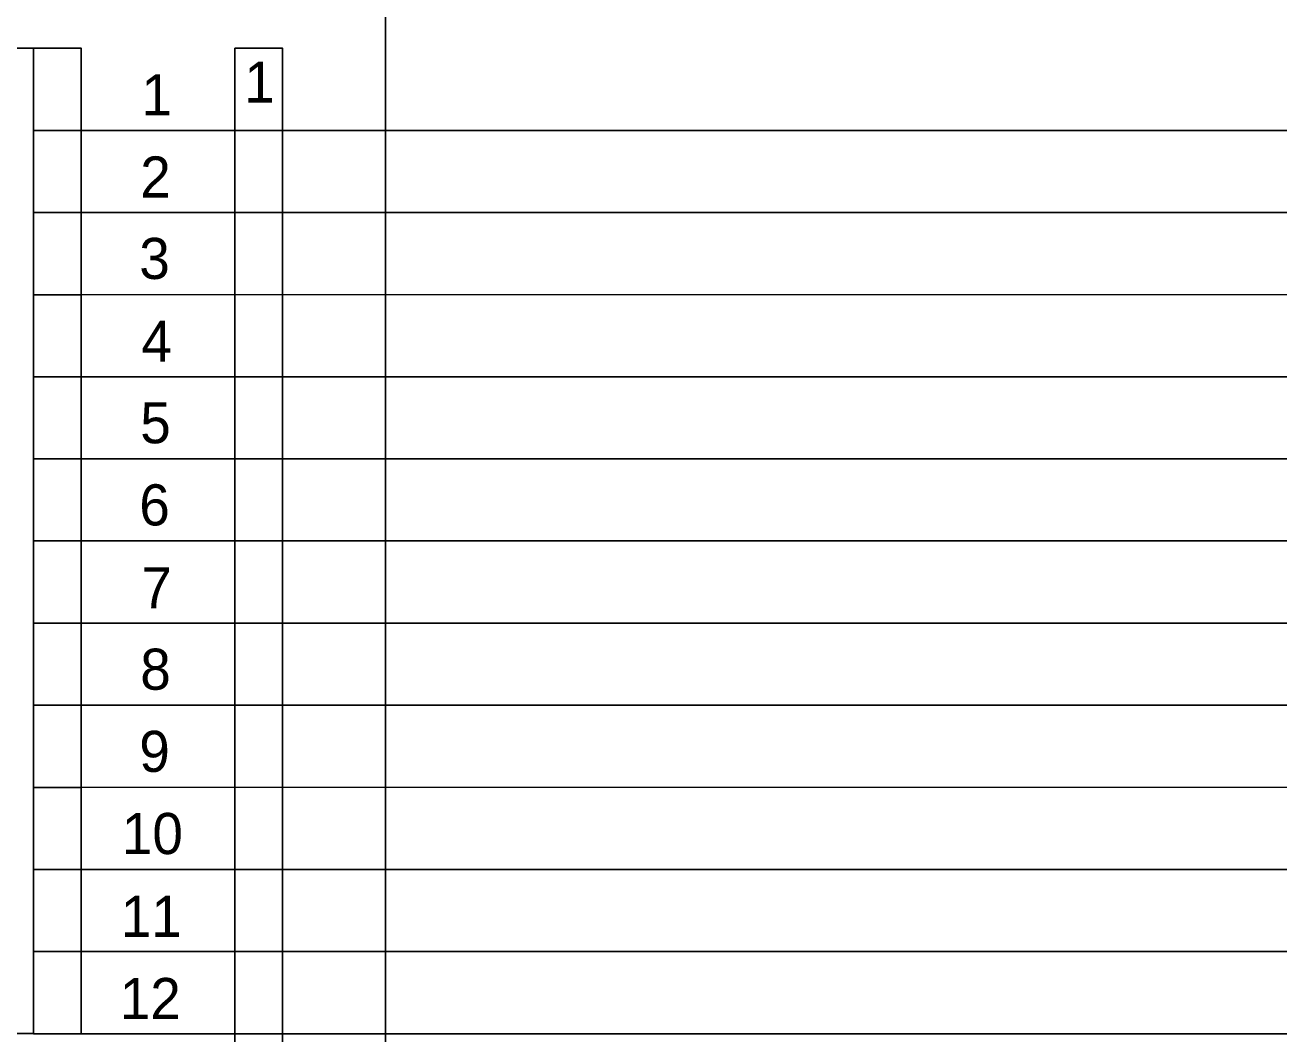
# Model space of a CAD drawing. Extents: x 1901 to 2519, y -3585 to -3154.
# Drawn here: x 2113 to 2166.7, y -3245.2 to -3202 of the extents above; entities that cross this region are included whole.
import ezdxf

# ---------------------------------------------------------------- set-up
doc = ezdxf.new("R2010")
doc.units = 0
doc.layers.add('rozvláknění', color=7, linetype='Continuous')

msp = doc.modelspace()

# ---------------------------------------------------------------- linework, layer by layer
at = {"layer": 'rozvláknění'}
for p, q in [((2115.435, -3206.527), (2247.063, -3206.526)), ((2115.435, -3210.045), (2247.063, -3210.044)), ((2115.435, -3213.563), (2247.063, -3213.562)), ((2115.435, -3217.081), (2247.063, -3217.08)), ((2115.435, -3220.599), (2247.063, -3220.598)), ((2115.435, -3224.117), (2247.063, -3224.117)), ((2115.435, -3227.636), (2247.063, -3227.635)), ((2115.435, -3231.154), (2247.063, -3231.153)), ((2115.435, -3234.672), (2247.063, -3234.671)), ((2115.435, -3238.19), (2247.063, -3238.189)), ((2115.435, -3241.708), (2247.063, -3241.708)), ((2115.435, -3245.227), (2247.063, -3245.226))]:
    msp.add_line(p, q, dxfattribs=at)
for points in [[(2094.462, -3178.545), (2128.46, -3178.544), (2128.46, -3571.465), (2094.462, -3571.465)], [(2110.606, -3203.008), (2113.393, -3203.008), (2113.393, -3245.223), (2110.606, -3245.223)], [(2113.393, -3203.008), (2115.435, -3203.008), (2115.435, -3206.527), (2113.393, -3206.527)], [(2113.393, -3203.008), (2115.435, -3203.008), (2115.435, -3206.527), (2113.393, -3206.527)], [(2124.059, -3287.481), (2122.017, -3287.481), (2122.017, -3203.008), (2124.059, -3203.008)], [(2124.059, -3245.227), (2122.017, -3245.227), (2122.017, -3203.008), (2124.059, -3203.008)], [(2113.393, -3206.527), (2115.435, -3206.527), (2115.435, -3210.045), (2113.393, -3210.045)], [(2113.393, -3206.527), (2115.435, -3206.527), (2115.435, -3210.045), (2113.393, -3210.045)], [(2113.393, -3210.045), (2115.435, -3210.045), (2115.435, -3213.563), (2113.393, -3213.563)], [(2113.393, -3210.045), (2115.435, -3210.045), (2115.435, -3213.563), (2113.393, -3213.563)], [(2113.393, -3213.563), (2115.435, -3213.563), (2115.435, -3217.081), (2113.393, -3217.081)], [(2113.393, -3213.563), (2115.435, -3213.563), (2115.435, -3217.081), (2113.393, -3217.081)], [(2113.393, -3217.081), (2115.435, -3217.081), (2115.435, -3220.599), (2113.393, -3220.599)], [(2113.393, -3217.081), (2115.435, -3217.081), (2115.435, -3220.599), (2113.393, -3220.599)], [(2113.393, -3220.599), (2115.435, -3220.599), (2115.435, -3224.117), (2113.393, -3224.117)], [(2113.393, -3220.599), (2115.435, -3220.599), (2115.435, -3224.117), (2113.393, -3224.117)], [(2113.393, -3224.117), (2115.435, -3224.117), (2115.435, -3227.636), (2113.393, -3227.636)], [(2113.393, -3224.117), (2115.435, -3224.117), (2115.435, -3227.636), (2113.393, -3227.636)], [(2113.393, -3227.636), (2115.435, -3227.636), (2115.435, -3231.154), (2113.393, -3231.154)], [(2113.393, -3227.636), (2115.435, -3227.636), (2115.435, -3231.154), (2113.393, -3231.154)], [(2113.393, -3231.154), (2115.435, -3231.154), (2115.435, -3234.672), (2113.393, -3234.672)], [(2113.393, -3231.154), (2115.435, -3231.154), (2115.435, -3234.672), (2113.393, -3234.672)], [(2113.393, -3234.672), (2115.435, -3234.672), (2115.435, -3238.19), (2113.393, -3238.19)], [(2113.393, -3234.672), (2115.435, -3234.672), (2115.435, -3238.19), (2113.393, -3238.19)], [(2113.393, -3238.19), (2115.435, -3238.19), (2115.435, -3241.708), (2113.393, -3241.708)], [(2113.393, -3238.19), (2115.435, -3238.19), (2115.435, -3241.708), (2113.393, -3241.708)], [(2113.393, -3241.708), (2115.435, -3241.708), (2115.435, -3245.227), (2113.393, -3245.227)], [(2113.393, -3241.708), (2115.435, -3241.708), (2115.435, -3245.227), (2113.393, -3245.227)]]:
    msp.add_lwpolyline(points, close=True, dxfattribs=at)
for points in [[(2113.393, -3206.527), (2115.435, -3206.527), (2115.435, -3203.008), (2113.393, -3203.008), (2113.393, -3206.527)], [(2113.393, -3206.527), (2115.435, -3206.527), (2115.435, -3203.008), (2113.393, -3203.008), (2113.393, -3206.527)], [(2113.393, -3206.527), (2115.435, -3206.527), (2115.435, -3203.008), (2113.393, -3203.008), (2113.393, -3206.527)], [(2113.393, -3206.527), (2115.435, -3206.527), (2115.435, -3203.008), (2113.393, -3203.008), (2113.393, -3206.527)], [(2113.393, -3206.527), (2115.435, -3206.527), (2115.435, -3203.008), (2113.393, -3203.008), (2113.393, -3206.527)], [(2113.393, -3206.527), (2115.435, -3206.527), (2115.435, -3203.008), (2113.393, -3203.008), (2113.393, -3206.527)], [(2113.393, -3206.527), (2115.435, -3206.527), (2115.435, -3203.008), (2113.393, -3203.008), (2113.393, -3206.527)], [(2113.393, -3206.527), (2115.435, -3206.527), (2115.435, -3203.008), (2113.393, -3203.008), (2113.393, -3206.527)], [(2113.393, -3206.527), (2115.435, -3206.527), (2115.435, -3203.008), (2113.393, -3203.008), (2113.393, -3206.527)], [(2113.393, -3206.527), (2115.435, -3206.527), (2115.435, -3203.008), (2113.393, -3203.008), (2113.393, -3206.527)], [(2124.059, -3203.008), (2122.017, -3203.008), (2122.017, -3245.227), (2124.059, -3245.227), (2124.059, -3203.008)], [(2124.059, -3203.008), (2122.017, -3203.008), (2122.017, -3245.227), (2124.059, -3245.227), (2124.059, -3203.008)], [(2124.059, -3203.008), (2122.017, -3203.008), (2122.017, -3245.227), (2124.059, -3245.227), (2124.059, -3203.008)], [(2124.059, -3203.008), (2122.017, -3203.008), (2122.017, -3245.227), (2124.059, -3245.227), (2124.059, -3203.008)], [(2124.059, -3203.008), (2122.017, -3203.008), (2122.017, -3245.227), (2124.059, -3245.227), (2124.059, -3203.008)], [(2124.059, -3203.008), (2122.017, -3203.008), (2122.017, -3245.227), (2124.059, -3245.227), (2124.059, -3203.008)], [(2113.393, -3210.045), (2115.435, -3210.045), (2115.435, -3206.527), (2113.393, -3206.527), (2113.393, -3210.045)], [(2113.393, -3210.045), (2115.435, -3210.045), (2115.435, -3206.527), (2113.393, -3206.527), (2113.393, -3210.045)], [(2113.393, -3210.045), (2115.435, -3210.045), (2115.435, -3206.527), (2113.393, -3206.527), (2113.393, -3210.045)], [(2113.393, -3210.045), (2115.435, -3210.045), (2115.435, -3206.527), (2113.393, -3206.527), (2113.393, -3210.045)], [(2113.393, -3210.045), (2115.435, -3210.045), (2115.435, -3206.527), (2113.393, -3206.527), (2113.393, -3210.045)], [(2113.393, -3210.045), (2115.435, -3210.045), (2115.435, -3206.527), (2113.393, -3206.527), (2113.393, -3210.045)], [(2113.393, -3210.045), (2115.435, -3210.045), (2115.435, -3206.527), (2113.393, -3206.527), (2113.393, -3210.045)], [(2113.393, -3210.045), (2115.435, -3210.045), (2115.435, -3206.527), (2113.393, -3206.527), (2113.393, -3210.045)], [(2113.393, -3210.045), (2115.435, -3210.045), (2115.435, -3206.527), (2113.393, -3206.527), (2113.393, -3210.045)], [(2113.393, -3210.045), (2115.435, -3210.045), (2115.435, -3206.527), (2113.393, -3206.527), (2113.393, -3210.045)], [(2113.393, -3213.563), (2115.435, -3213.563), (2115.435, -3210.045), (2113.393, -3210.045), (2113.393, -3213.563)], [(2113.393, -3213.563), (2115.435, -3213.563), (2115.435, -3210.045), (2113.393, -3210.045), (2113.393, -3213.563)], [(2113.393, -3213.563), (2115.435, -3213.563), (2115.435, -3210.045), (2113.393, -3210.045), (2113.393, -3213.563)], [(2113.393, -3213.563), (2115.435, -3213.563), (2115.435, -3210.045), (2113.393, -3210.045), (2113.393, -3213.563)], [(2113.393, -3213.563), (2115.435, -3213.563), (2115.435, -3210.045), (2113.393, -3210.045), (2113.393, -3213.563)], [(2113.393, -3213.563), (2115.435, -3213.563), (2115.435, -3210.045), (2113.393, -3210.045), (2113.393, -3213.563)], [(2113.393, -3213.563), (2115.435, -3213.563), (2115.435, -3210.045), (2113.393, -3210.045), (2113.393, -3213.563)], [(2113.393, -3213.563), (2115.435, -3213.563), (2115.435, -3210.045), (2113.393, -3210.045), (2113.393, -3213.563)], [(2113.393, -3213.563), (2115.435, -3213.563), (2115.435, -3210.045), (2113.393, -3210.045), (2113.393, -3213.563)], [(2113.393, -3213.563), (2115.435, -3213.563), (2115.435, -3210.045), (2113.393, -3210.045), (2113.393, -3213.563)], [(2113.393, -3217.081), (2115.435, -3217.081), (2115.435, -3213.563), (2113.393, -3213.563), (2113.393, -3217.081)], [(2113.393, -3217.081), (2115.435, -3217.081), (2115.435, -3213.563), (2113.393, -3213.563), (2113.393, -3217.081)], [(2113.393, -3217.081), (2115.435, -3217.081), (2115.435, -3213.563), (2113.393, -3213.563), (2113.393, -3217.081)], [(2113.393, -3217.081), (2115.435, -3217.081), (2115.435, -3213.563), (2113.393, -3213.563), (2113.393, -3217.081)], [(2113.393, -3217.081), (2115.435, -3217.081), (2115.435, -3213.563), (2113.393, -3213.563), (2113.393, -3217.081)], [(2113.393, -3217.081), (2115.435, -3217.081), (2115.435, -3213.563), (2113.393, -3213.563), (2113.393, -3217.081)], [(2113.393, -3217.081), (2115.435, -3217.081), (2115.435, -3213.563), (2113.393, -3213.563), (2113.393, -3217.081)], [(2113.393, -3217.081), (2115.435, -3217.081), (2115.435, -3213.563), (2113.393, -3213.563), (2113.393, -3217.081)], [(2113.393, -3217.081), (2115.435, -3217.081), (2115.435, -3213.563), (2113.393, -3213.563), (2113.393, -3217.081)], [(2113.393, -3217.081), (2115.435, -3217.081), (2115.435, -3213.563), (2113.393, -3213.563), (2113.393, -3217.081)], [(2113.393, -3220.599), (2115.435, -3220.599), (2115.435, -3217.081), (2113.393, -3217.081), (2113.393, -3220.599)], [(2113.393, -3220.599), (2115.435, -3220.599), (2115.435, -3217.081), (2113.393, -3217.081), (2113.393, -3220.599)], [(2113.393, -3220.599), (2115.435, -3220.599), (2115.435, -3217.081), (2113.393, -3217.081), (2113.393, -3220.599)], [(2113.393, -3220.599), (2115.435, -3220.599), (2115.435, -3217.081), (2113.393, -3217.081), (2113.393, -3220.599)], [(2113.393, -3220.599), (2115.435, -3220.599), (2115.435, -3217.081), (2113.393, -3217.081), (2113.393, -3220.599)], [(2113.393, -3220.599), (2115.435, -3220.599), (2115.435, -3217.081), (2113.393, -3217.081), (2113.393, -3220.599)], [(2113.393, -3220.599), (2115.435, -3220.599), (2115.435, -3217.081), (2113.393, -3217.081), (2113.393, -3220.599)], [(2113.393, -3220.599), (2115.435, -3220.599), (2115.435, -3217.081), (2113.393, -3217.081), (2113.393, -3220.599)], [(2113.393, -3220.599), (2115.435, -3220.599), (2115.435, -3217.081), (2113.393, -3217.081), (2113.393, -3220.599)], [(2113.393, -3220.599), (2115.435, -3220.599), (2115.435, -3217.081), (2113.393, -3217.081), (2113.393, -3220.599)], [(2113.393, -3224.117), (2115.435, -3224.117), (2115.435, -3220.599), (2113.393, -3220.599), (2113.393, -3224.117)], [(2113.393, -3224.117), (2115.435, -3224.117), (2115.435, -3220.599), (2113.393, -3220.599), (2113.393, -3224.117)], [(2113.393, -3224.117), (2115.435, -3224.117), (2115.435, -3220.599), (2113.393, -3220.599), (2113.393, -3224.117)], [(2113.393, -3224.117), (2115.435, -3224.117), (2115.435, -3220.599), (2113.393, -3220.599), (2113.393, -3224.117)], [(2113.393, -3224.117), (2115.435, -3224.117), (2115.435, -3220.599), (2113.393, -3220.599), (2113.393, -3224.117)], [(2113.393, -3224.117), (2115.435, -3224.117), (2115.435, -3220.599), (2113.393, -3220.599), (2113.393, -3224.117)], [(2113.393, -3224.117), (2115.435, -3224.117), (2115.435, -3220.599), (2113.393, -3220.599), (2113.393, -3224.117)], [(2113.393, -3224.117), (2115.435, -3224.117), (2115.435, -3220.599), (2113.393, -3220.599), (2113.393, -3224.117)], [(2113.393, -3224.117), (2115.435, -3224.117), (2115.435, -3220.599), (2113.393, -3220.599), (2113.393, -3224.117)], [(2113.393, -3224.117), (2115.435, -3224.117), (2115.435, -3220.599), (2113.393, -3220.599), (2113.393, -3224.117)], [(2113.393, -3227.636), (2115.435, -3227.636), (2115.435, -3224.117), (2113.393, -3224.117), (2113.393, -3227.636)], [(2113.393, -3227.636), (2115.435, -3227.636), (2115.435, -3224.117), (2113.393, -3224.117), (2113.393, -3227.636)], [(2113.393, -3227.636), (2115.435, -3227.636), (2115.435, -3224.117), (2113.393, -3224.117), (2113.393, -3227.636)], [(2113.393, -3227.636), (2115.435, -3227.636), (2115.435, -3224.117), (2113.393, -3224.117), (2113.393, -3227.636)], [(2113.393, -3227.636), (2115.435, -3227.636), (2115.435, -3224.117), (2113.393, -3224.117), (2113.393, -3227.636)], [(2113.393, -3227.636), (2115.435, -3227.636), (2115.435, -3224.117), (2113.393, -3224.117), (2113.393, -3227.636)], [(2113.393, -3227.636), (2115.435, -3227.636), (2115.435, -3224.117), (2113.393, -3224.117), (2113.393, -3227.636)], [(2113.393, -3227.636), (2115.435, -3227.636), (2115.435, -3224.117), (2113.393, -3224.117), (2113.393, -3227.636)], [(2113.393, -3227.636), (2115.435, -3227.636), (2115.435, -3224.117), (2113.393, -3224.117), (2113.393, -3227.636)], [(2113.393, -3227.636), (2115.435, -3227.636), (2115.435, -3224.117), (2113.393, -3224.117), (2113.393, -3227.636)], [(2113.393, -3231.154), (2115.435, -3231.154), (2115.435, -3227.636), (2113.393, -3227.636), (2113.393, -3231.154)], [(2113.393, -3231.154), (2115.435, -3231.154), (2115.435, -3227.636), (2113.393, -3227.636), (2113.393, -3231.154)], [(2113.393, -3231.154), (2115.435, -3231.154), (2115.435, -3227.636), (2113.393, -3227.636), (2113.393, -3231.154)], [(2113.393, -3231.154), (2115.435, -3231.154), (2115.435, -3227.636), (2113.393, -3227.636), (2113.393, -3231.154)], [(2113.393, -3231.154), (2115.435, -3231.154), (2115.435, -3227.636), (2113.393, -3227.636), (2113.393, -3231.154)], [(2113.393, -3231.154), (2115.435, -3231.154), (2115.435, -3227.636), (2113.393, -3227.636), (2113.393, -3231.154)], [(2113.393, -3231.154), (2115.435, -3231.154), (2115.435, -3227.636), (2113.393, -3227.636), (2113.393, -3231.154)], [(2113.393, -3231.154), (2115.435, -3231.154), (2115.435, -3227.636), (2113.393, -3227.636), (2113.393, -3231.154)], [(2113.393, -3231.154), (2115.435, -3231.154), (2115.435, -3227.636), (2113.393, -3227.636), (2113.393, -3231.154)], [(2113.393, -3231.154), (2115.435, -3231.154), (2115.435, -3227.636), (2113.393, -3227.636), (2113.393, -3231.154)], [(2113.393, -3234.672), (2115.435, -3234.672), (2115.435, -3231.154), (2113.393, -3231.154), (2113.393, -3234.672)], [(2113.393, -3234.672), (2115.435, -3234.672), (2115.435, -3231.154), (2113.393, -3231.154), (2113.393, -3234.672)], [(2113.393, -3234.672), (2115.435, -3234.672), (2115.435, -3231.154), (2113.393, -3231.154), (2113.393, -3234.672)], [(2113.393, -3234.672), (2115.435, -3234.672), (2115.435, -3231.154), (2113.393, -3231.154), (2113.393, -3234.672)], [(2113.393, -3234.672), (2115.435, -3234.672), (2115.435, -3231.154), (2113.393, -3231.154), (2113.393, -3234.672)], [(2113.393, -3234.672), (2115.435, -3234.672), (2115.435, -3231.154), (2113.393, -3231.154), (2113.393, -3234.672)], [(2113.393, -3234.672), (2115.435, -3234.672), (2115.435, -3231.154), (2113.393, -3231.154), (2113.393, -3234.672)], [(2113.393, -3234.672), (2115.435, -3234.672), (2115.435, -3231.154), (2113.393, -3231.154), (2113.393, -3234.672)], [(2113.393, -3234.672), (2115.435, -3234.672), (2115.435, -3231.154), (2113.393, -3231.154), (2113.393, -3234.672)], [(2113.393, -3234.672), (2115.435, -3234.672), (2115.435, -3231.154), (2113.393, -3231.154), (2113.393, -3234.672)], [(2113.393, -3238.19), (2115.435, -3238.19), (2115.435, -3234.672), (2113.393, -3234.672), (2113.393, -3238.19)], [(2113.393, -3238.19), (2115.435, -3238.19), (2115.435, -3234.672), (2113.393, -3234.672), (2113.393, -3238.19)], [(2113.393, -3238.19), (2115.435, -3238.19), (2115.435, -3234.672), (2113.393, -3234.672), (2113.393, -3238.19)], [(2113.393, -3238.19), (2115.435, -3238.19), (2115.435, -3234.672), (2113.393, -3234.672), (2113.393, -3238.19)], [(2113.393, -3238.19), (2115.435, -3238.19), (2115.435, -3234.672), (2113.393, -3234.672), (2113.393, -3238.19)], [(2113.393, -3238.19), (2115.435, -3238.19), (2115.435, -3234.672), (2113.393, -3234.672), (2113.393, -3238.19)], [(2113.393, -3238.19), (2115.435, -3238.19), (2115.435, -3234.672), (2113.393, -3234.672), (2113.393, -3238.19)], [(2113.393, -3238.19), (2115.435, -3238.19), (2115.435, -3234.672), (2113.393, -3234.672), (2113.393, -3238.19)], [(2113.393, -3238.19), (2115.435, -3238.19), (2115.435, -3234.672), (2113.393, -3234.672), (2113.393, -3238.19)], [(2113.393, -3238.19), (2115.435, -3238.19), (2115.435, -3234.672), (2113.393, -3234.672), (2113.393, -3238.19)], [(2113.393, -3241.708), (2115.435, -3241.708), (2115.435, -3238.19), (2113.393, -3238.19), (2113.393, -3241.708)], [(2113.393, -3241.708), (2115.435, -3241.708), (2115.435, -3238.19), (2113.393, -3238.19), (2113.393, -3241.708)], [(2113.393, -3241.708), (2115.435, -3241.708), (2115.435, -3238.19), (2113.393, -3238.19), (2113.393, -3241.708)], [(2113.393, -3241.708), (2115.435, -3241.708), (2115.435, -3238.19), (2113.393, -3238.19), (2113.393, -3241.708)], [(2113.393, -3241.708), (2115.435, -3241.708), (2115.435, -3238.19), (2113.393, -3238.19), (2113.393, -3241.708)], [(2113.393, -3241.708), (2115.435, -3241.708), (2115.435, -3238.19), (2113.393, -3238.19), (2113.393, -3241.708)], [(2113.393, -3241.708), (2115.435, -3241.708), (2115.435, -3238.19), (2113.393, -3238.19), (2113.393, -3241.708)], [(2113.393, -3241.708), (2115.435, -3241.708), (2115.435, -3238.19), (2113.393, -3238.19), (2113.393, -3241.708)], [(2113.393, -3241.708), (2115.435, -3241.708), (2115.435, -3238.19), (2113.393, -3238.19), (2113.393, -3241.708)], [(2113.393, -3241.708), (2115.435, -3241.708), (2115.435, -3238.19), (2113.393, -3238.19), (2113.393, -3241.708)], [(2113.393, -3245.227), (2115.435, -3245.227), (2115.435, -3241.708), (2113.393, -3241.708), (2113.393, -3245.227)], [(2113.393, -3245.227), (2115.435, -3245.227), (2115.435, -3241.708), (2113.393, -3241.708), (2113.393, -3245.227)], [(2113.393, -3245.227), (2115.435, -3245.227), (2115.435, -3241.708), (2113.393, -3241.708), (2113.393, -3245.227)], [(2113.393, -3245.227), (2115.435, -3245.227), (2115.435, -3241.708), (2113.393, -3241.708), (2113.393, -3245.227)], [(2113.393, -3245.227), (2115.435, -3245.227), (2115.435, -3241.708), (2113.393, -3241.708), (2113.393, -3245.227)], [(2113.393, -3245.227), (2115.435, -3245.227), (2115.435, -3241.708), (2113.393, -3241.708), (2113.393, -3245.227)], [(2113.393, -3245.227), (2115.435, -3245.227), (2115.435, -3241.708), (2113.393, -3241.708), (2113.393, -3245.227)], [(2113.393, -3245.227), (2115.435, -3245.227), (2115.435, -3241.708), (2113.393, -3241.708), (2113.393, -3245.227)], [(2113.393, -3245.227), (2115.435, -3245.227), (2115.435, -3241.708), (2113.393, -3241.708), (2113.393, -3245.227)], [(2113.393, -3245.227), (2115.435, -3245.227), (2115.435, -3241.708), (2113.393, -3241.708), (2113.393, -3245.227)]]:
    msp.add_lwpolyline(points, dxfattribs=at)

# ---------------------------------------------------------------- texts
for s, p in [('1', (2122.416, -3205.334)), ('1', (2122.416, -3205.334)), ('1', (2118.008, -3205.88)), ('2', (2117.961, -3209.4)), ('3', (2117.919, -3212.89)), ('4', (2118.008, -3216.44)), ('5', (2117.961, -3219.93)), ('6', (2117.919, -3223.45)), ('7', (2118.008, -3227)), ('8', (2117.961, -3230.49)), ('9', (2117.919, -3234.01)), ('10', (2117.171, -3237.53)), ('11', (2117.124, -3241.08)), ('12', (2117.082, -3244.6))]:
    msp.add_text(s, height=1.76, dxfattribs=at).set_placement(p)

doc.saveas('drawing.dxf')
